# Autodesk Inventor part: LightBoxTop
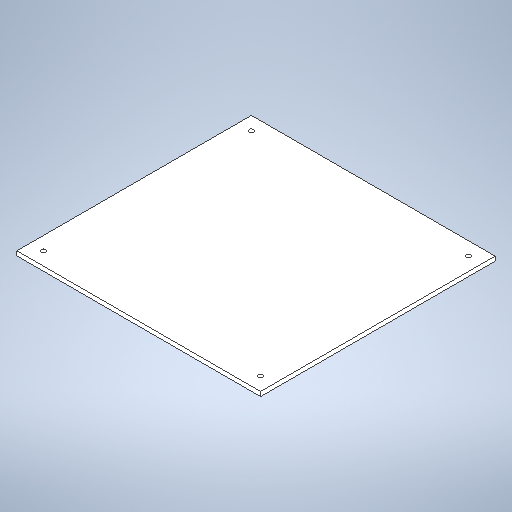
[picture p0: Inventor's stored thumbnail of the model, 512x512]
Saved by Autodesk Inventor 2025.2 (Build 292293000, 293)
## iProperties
Created: 2025-09
Part Number: LightBoxTop
Material: Generic
Document SubType Name: Modeling
Designer: tyler
Density: 1 g/cm^3
Appearance: Default
Author: tyler
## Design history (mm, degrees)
sketch "Sketch1"
  geometry: 1 further point
sketch "Sketch2"
  geometry: L1 (-175.133, 168.529)-(175.133, 168.529); L2 (175.133, 168.529)-(175.133, -168.529); L3 (175.133, -168.529)-(-175.133, -168.529); L4 (-175.133, -168.529)-(-175.133, 168.529); L5 (-175.133, 168.529)-(175.133, -168.529); L6 (175.133, 168.529)-(-175.133, -168.529); 1 further point
  constraints: 12 end point, 2 midpoint, 2 parallel, 1 horizontal, 1 perpendicular
  dimensions: "d0" = 350.266 distance of L2.end L3.end; "d1" = 337.058 distance of L1.end L2.end
extrude "Extrusion1" new body sketch "Sketch2" distance "d2" = 6.35; taper "d3" = 0 deg
sketch "Sketch3"
  geometry: L1 (-175.133, 168.529)-(-175.133, -168.529) reference; L2 (-175.133, -168.529)-(-175.133, -149.479); L3 (-175.133, -149.479)-(-156.083, -149.479); L4 (-175.133, -168.529)-(175.133, -168.529) reference; L5 (175.133, -168.529)-(175.133, -149.479); L6 (175.133, -168.529)-(175.133, 168.529) reference; L7 (175.133, -149.479)-(156.083, -149.479); L8 (-175.133, 0)-(-156.083, 0); C1 r 3.175 at (-156.083, -149.479); C2 r 3.175 at (156.083, -149.479); C3 r 3.175 at (-156.083, 149.479); C4 r 3.175 at (156.083, 149.479); 1 further point
  constraints: 10 end point, 4 centre point, 2 coincident, 2 perpendicular, 2 point on line, 2 symmetric about line, 1 horizontal, 1 midpoint, 2 other
  dimensions: "d4" = 19.05 distance of L1.end L2.end; "d5" = 19.05 distance of L2.end L3.end; "d6" = 19.05 distance of L4.end L5.end; "d7" = 19.05 distance of L5.end L7.end; "d8" = 6.35 diameter of C1; "d9" = 6.35 diameter of C2
extrude "Extrusion2" cut sketch "Sketch3" distance "d10" = 6.35; taper "d11" = 0 deg
body "Solid1"
